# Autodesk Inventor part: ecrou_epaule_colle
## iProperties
Created: 2011-01
Part Number: ecrou_epaule_colle
Document SubType Name: Modeling
Designer: eric
Density: 1 g/cm^3
Mass: 0.0543888 g
Surface Area: 1.20559 cm^2
Volume: 0.0543888 cm^3
Author: eric
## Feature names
1. Base1
